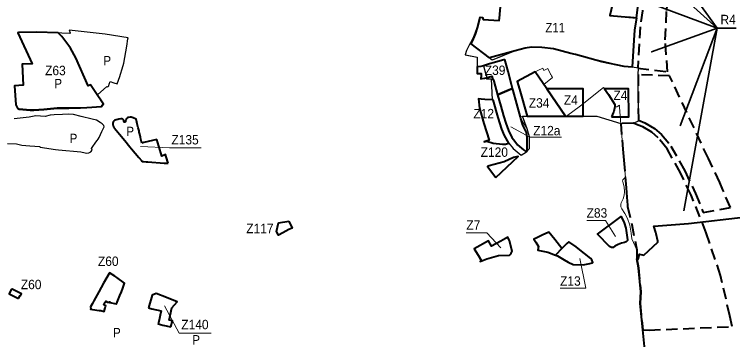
# Model space of a CAD drawing. Extents: x -650276 to -642489, y -1074425 to -1066658.
# Drawn here: x -647044 to -645214, y -1070685 to -1069855 of the extents above; entities that cross this region are included whole.
import ezdxf

# ---------------------------------------------------------------- set-up
doc = ezdxf.new("R2010")
doc.units = 0
doc.header["$LTSCALE"] = 9.6
doc.linetypes.add('MEDIUM_DASHED', pattern=[4.5, 3, -1.5])
for name, color, linetype, lineweight in [('1', 7, 'Continuous', 13), ('4', 7, 'Continuous', 40), ('42', 7, 'Continuous', 25), ('44', 7, 'Continuous', 40), ('45', 7, 'Continuous', 40), ('46', 7, 'Continuous', 13), ('5', 7, 'Continuous', 35), ('60', 7, 'Continuous', 35), ('61', 7, 'MEDIUM_DASHED', 40), ('62', 7, 'Continuous', 35), ('7', 7, 'MEDIUM_DASHED', 40)]:
    doc.layers.add(name, color=color, linetype=linetype, lineweight=lineweight)

msp = doc.modelspace()

# ---------------------------------------------------------------- linework, layer by layer
at = {"layer": '1'}
for points in [[(-645494.12, -1070282.52), (-645494.57, -1070280.34), (-645493.8, -1070277.67), (-645491.94, -1070275.85), (-645487.361, -1070271.37), (-645490.95, -1070226.89), (-645497.23, -1070154.58), (-645499.84, -1070125.33), (-645502.55, -1070091.83), (-645503.04, -1070089.54), (-645502.17, -1070089.16), (-645502.45, -1070087.23), (-645504.06, -1070087.92), (-645509.06, -1070090.97), (-645514.56, -1070090.91), (-645514.49, -1070085.4), (-645530.3, -1070060.08), (-645543.32, -1070041.67), (-645601.8, -1070088.57), (-645637.56, -1070114.89), (-645683.72, -1070114.92), (-645744.39, -1070114.96), (-645749.28, -1070114.96), (-645755.4, -1070117.6), (-645744.75, -1070135.39), (-645737.63, -1070147.39), (-645731.94, -1070167.87), (-645731.3, -1070197.24), (-645739.12, -1070205.9), (-645752.54, -1070214.74), (-645773.48, -1070197.1), (-645784.51, -1070183.77), (-645795.07, -1070164.26), (-645801.99, -1070148.51), (-645811.48, -1070118.65), (-645824.28, -1070073.67), (-645826.615, -1070073.495), (-645828.963, -1070019.709), (-645841.075, -1070020.163), (-645841.89, -1070017.42), (-645841.21, -1070017.31), (-645841.32, -1070013.79), (-645841.43, -1070010.21), (-645842.34, -1070010.22), (-645843.74, -1070010.25), (-645842.8, -1070008.59), (-645849.1, -1069986.42), (-645855.54, -1069988.24), (-645864.77, -1069989.26), (-645864.48, -1069964.53), (-645894.25, -1069958.7), (-645895.66, -1069958.42), (-645892.09, -1069947.98), (-645876.15, -1069916.47), (-645870.89, -1069903.5), (-645865.78, -1069888.76), (-645858.78, -1069862.84), (-645850.92, -1069863.41), (-645849.79, -1069868.4), (-645808.84, -1069870.75), (-645808.28, -1069865.39), (-645806.07, -1069844.09)], [(-645695.39, -1070034), (-645673.1, -1070016.78), (-645675.24, -1070012.51), (-645677.02, -1070008.93), (-645677.65, -1070007.66), (-645684.59, -1069993.87), (-645689.84, -1069996.37), (-645694.8, -1069998.22), (-645697.59, -1069992.31), (-645710.43, -1069998.39), (-645717.36, -1070002.12)], [(-645717.36, -1070002.12), (-645706.41, -1070018.01), (-645695.39, -1070034)], [(-645470.99, -1070428.07), (-645472.61, -1070413.13), (-645476.12, -1070393.13), (-645482.16, -1070375.96), (-645488.99, -1070362.96), (-645496.02, -1070351.15), (-645498, -1070347.74), (-645498.74, -1070345.87), (-645499.09, -1070343.91), (-645499.01, -1070340.96), (-645498.75, -1070338.98), (-645497.83, -1070336.16), (-645495.44, -1070330.67), (-645493.05, -1070326.11), (-645490.03, -1070316.27), (-645489.31, -1070307.77), (-645490.79, -1070294.93), (-645494.12, -1070282.52)], [(-645428.73, -1070758.67), (-645434.53, -1070738.77), (-645449.82, -1070592.72), (-645448.36, -1070563), (-645454.02, -1070501.52), (-645458.46, -1070478.86), (-645458.32, -1070455.91), (-645470.99, -1070428.07)]]:
    msp.add_lwpolyline(points, dxfattribs=at)
at = {"layer": '4'}
for points in [[(-646791.03, -1070128.23), (-646791.64, -1070129), (-646792.11, -1070129.89), (-646792.76, -1070131.79), (-646792.97, -1070133.76), (-646792.84, -1070135.73), (-646792.42, -1070137.71), (-646792.18, -1070138.48), (-646791.84, -1070139.56), (-646791.13, -1070141.44), (-646790.86, -1070142.02), (-646790.29, -1070142.85), (-646784.8, -1070149.86), (-646784.45, -1070150.291)], [(-646748.31, -1070117.83), (-646753.45, -1070118.63), (-646755.74, -1070119.56), (-646757.76, -1070121.07), (-646759.06, -1070122.6), (-646759.78, -1070124), (-646760.32, -1070125.55), (-646760.5, -1070127.58), (-646760.22, -1070129.42), (-646762.07, -1070129.91), (-646763.9, -1070130.41), (-646763.98, -1070130.1), (-646764, -1070129.86), (-646764.94, -1070127.21), (-646765.19, -1070126.23), (-646765.51, -1070125.28), (-646765.97, -1070124.42), (-646767.38, -1070123), (-646768.25, -1070122.53), (-646769.17, -1070122.15), (-646770.43, -1070121.92), (-646772.19, -1070121.98), (-646777.37, -1070122.79), (-646780.28, -1070123.41), (-646784.13, -1070124.41), (-646787, -1070125.38), (-646788.77, -1070126.26), (-646789.61, -1070126.79), (-646791.03, -1070128.23)], [(-646718.8, -1070183.56), (-646721.09, -1070173.94), (-646722.4, -1070168.45), (-646723.4, -1070164.29), (-646724.86, -1070158.17), (-646725.39, -1070155.78), (-646726.17, -1070152.7), (-646728.14, -1070144.51), (-646730.45, -1070134.85), (-646731.54, -1070130.28), (-646733.35, -1070122.79), (-646740.92, -1070119.57), (-646743.33, -1070118.51), (-646745.78, -1070117.96), (-646748.31, -1070117.83)], [(-646784.45, -1070150.291), (-646784.18, -1070150.61), (-646783.937, -1070150.923), (-646775.93, -1070160.78), (-646762.52, -1070177.24)], [(-646762.52, -1070177.24), (-646749.79, -1070193.02), (-646745.61, -1070198.15), (-646726.48, -1070220.46), (-646726.36, -1070220.34), (-646719.7, -1070228.25), (-646717.71, -1070230.56)], [(-646680.68, -1070174.5), (-646713.74, -1070182.36), (-646718.8, -1070183.56)], [(-646651.86, -1070235.22), (-646656.96, -1070218.43), (-646658.64, -1070212.77), (-646667.64, -1070217.36), (-646680.61, -1070174.79), (-646680.68, -1070174.5)], [(-646717.71, -1070230.56), (-646714.42, -1070230.81), (-646708.2, -1070231.25), (-646703.67, -1070231.58), (-646662.41, -1070234.57), (-646651.86, -1070235.22)], [(-646655.95, -1070577.64), (-646682.29, -1070567.36), (-646692.98, -1070571.45), (-646701.87, -1070603.92)], [(-646649.71, -1070634.85), (-646642.32, -1070603.3), (-646628.69, -1070588.27), (-646655.95, -1070577.64)], [(-646701.87, -1070603.92), (-646693.18, -1070605.83), (-646669.59, -1070611.01)], [(-646669.59, -1070611.01), (-646672.13, -1070622.41), (-646673.91, -1070630.38), (-646676.414, -1070641.58)], [(-646676.414, -1070641.58), (-646676.81, -1070643.36), (-646677.13, -1070644.78), (-646665.42, -1070647.54), (-646645.03, -1070652.34)], [(-646645.03, -1070652.34), (-646641.09, -1070636.89), (-646649.71, -1070634.85)]]:
    msp.add_lwpolyline(points, dxfattribs=at)
at = {"layer": '4', "lineweight": 13}
for points in [[(-646567.835, -1070195.719), (-646648.755, -1070195.719), (-646722.263, -1070192.418)], [(-646542.723, -1070668.026), (-646623.643, -1070668.026), (-646660.881, -1070598.727)]]:
    msp.add_lwpolyline(points, dxfattribs=at)
at = {"layer": '42'}
for points in [[(-646753.995, -1069915.425), (-646811.935, -1069906.155), (-646904.446, -1069895.991), (-646901.388, -1069902.723), (-646902.06, -1069902.694), (-646901.388, -1069904.174)], [(-646901.388, -1069904.174), (-646987.56, -1069900.52), (-647032.16, -1069902.13), (-647033.853, -1069902.188)], [(-647033.853, -1069902.188), (-646998.06, -1069980.039), (-646998.716, -1069980.064)], [(-646831.912, -1070060.406), (-646808.49, -1070039.689), (-646805.65, -1070040.439), (-646803.87, -1070038.879), (-646803.43, -1070037.629), (-646801.84, -1070033.139), (-646799.45, -1070026.749), (-646790.27, -1070029.749), (-646781.39, -1070032.779), (-646774.86, -1070014.019), (-646772.96, -1070007.579), (-646768.91, -1069993.979), (-646764.81, -1069980.189), (-646757.45, -1069936.669), (-646754.36, -1069917.669), (-646753.995, -1069915.425)], [(-646998.716, -1069980.064), (-646998.06, -1069981.49), (-647023.975, -1069982.477)], [(-647023.975, -1069982.477), (-647021.27, -1070034.829), (-647021.345, -1070034.832)], [(-647021.345, -1070034.832), (-647021.27, -1070036.28), (-647043.157, -1070037.286)], [(-647043.157, -1070037.286), (-647040.12, -1070084.659), (-647036.03, -1070093.509), (-647034.17, -1070095.039), (-647031.73, -1070095.759), (-647003.49, -1070098.209), (-646993.92, -1070098.039), (-646968.89, -1070096.569), (-646934.63, -1070092.789), (-646904.97, -1070093.069)], [(-646904.97, -1070093.069), (-646874.9, -1070092.649), (-646859.29, -1070091.649), (-646821.89, -1070089.249), (-646817.427, -1070083.656), (-646831.912, -1070061.857), (-646831.305, -1070061.32), (-646831.912, -1070060.406)], [(-647061.2, -1070184.6), (-647038.31, -1070185.73), (-647024.2, -1070188.68), (-647003.89, -1070190.89), (-646978.73, -1070192.54), (-646978.72, -1070193.6), (-646977.7, -1070193.62), (-646977.7, -1070194.45), (-646938.98, -1070199.89), (-646931.25, -1070200.56), (-646874.04, -1070205.5), (-646863.66, -1070208.37), (-646859.54, -1070209.09), (-646853.67, -1070208.44), (-646849.15, -1070205.9), (-646845.3, -1070201.3), (-646847.17, -1070197.38), (-646845.76, -1070194.67), (-646836.06, -1070181.31), (-646832.62, -1070177.08), (-646829.87, -1070173.61), (-646827.95, -1070169.52), (-646820.51, -1070153.68), (-646814.53, -1070141.96), (-646816.06, -1070138.5), (-646820.35, -1070134.43), (-646825.4, -1070130.78), (-646834.04, -1070125.34), (-646845.78, -1070122.84), (-646873.5, -1070115.8), (-646892.87, -1070110.82), (-646904.66, -1070110.24), (-646920.68, -1070110.58), (-646941.99, -1070111.74), (-646952.66, -1070112.57), (-646965.6, -1070115.74), (-646989.24, -1070114.17), (-646989.24, -1070114.17), (-647005.97, -1070117.89), (-647044.19, -1070121.78)]]:
    msp.add_lwpolyline(points, dxfattribs=at)
msp.add_lwpolyline([(-645637.56, -1070114.89), (-645559.63, -1070114.85), (-645499.129, -1070133.293), (-645466.862, -1070133.219), (-645454.051, -1070127.008), (-645455.073, -1070009.111), (-645453.852, -1069992.968), (-645469.701, -1069990.011), (-645490.814, -1069988.074), (-645601.753, -1069962.317), (-645614.072, -1069957.797), (-645625.979, -1069954.92), (-645670.325, -1069943.002), (-645699.889, -1069939.714), (-645726.542, -1069939.398), (-645742.967, -1069941.862), (-645768.424, -1069948.431), (-645826.321, -1069972.247), (-645880.431, -1069930.3), (-645882.381, -1069928.788), (-645892.09, -1069947.98), (-645895.66, -1069958.42), (-645864.48, -1069964.53), (-645864.77, -1069989.26), (-645855.54, -1069988.24), (-645849.1, -1069986.42), (-645842.8, -1070008.59), (-645843.74, -1070010.25), (-645841.43, -1070010.21), (-645841.21, -1070017.31), (-645841.89, -1070017.42), (-645841.075, -1070020.163), (-645828.963, -1070019.709), (-645826.615, -1070073.495), (-645824.28, -1070073.67), (-645811.48, -1070118.65), (-645801.99, -1070148.51), (-645795.07, -1070164.26), (-645784.51, -1070183.77), (-645773.48, -1070197.1), (-645752.54, -1070214.74), (-645739.12, -1070205.9), (-645731.3, -1070197.24), (-645731.94, -1070167.87), (-645737.63, -1070147.39), (-645749.28, -1070114.96), (-645737.075, -1070114.955)], close=True, dxfattribs=at)
at = {"layer": '44'}
msp.add_lwpolyline([(-645497.81, -1070370.93), (-645497.81, -1070370.93), (-645490.19, -1070386.97), (-645486.54, -1070400.38), (-645483.29, -1070417.99), (-645482.62, -1070423.93), (-645481.93, -1070430.04), (-645482.18, -1070432.13), (-645485.67, -1070435.7), (-645489.34, -1070437.05), (-645497.33, -1070438.82), (-645505.88, -1070441.74), (-645513.81, -1070446.24), (-645517.44, -1070449.23), (-645517.95, -1070449.45), (-645520.4, -1070449.87), (-645521.41, -1070449.84), (-645522.95, -1070449.61), (-645524.42, -1070449.16), (-645525.75, -1070448.41), (-645527.34, -1070447.1), (-645558.36, -1070416.1)], close=True, dxfattribs=at)
at = {"layer": '44', "lineweight": 13}
msp.add_lwpolyline([(-645585.63, -1070380.811), (-645537.799, -1070380.811), (-645512.608, -1070421.471)], dxfattribs=at)
msp.add_lwpolyline([(-645585.63, -1070380.811), (-645537.799, -1070380.811), (-645512.608, -1070421.471)], dxfattribs=at)
at = {"layer": '45'}
msp.add_line((-645726.542, -1069939.398), (-645742.967, -1069941.862), dxfattribs=at)
for points in [[(-645500.137, -1069632.833), (-645498, -1069648), (-645495, -1069688), (-645495, -1069744), (-645495, -1069766), (-645504.976, -1069763.332), (-645527, -1069858), (-645459.312, -1069864.01), (-645464.288, -1069895.362), (-645465.756, -1069921.035), (-645469.701, -1069990.011)], [(-645742.967, -1069941.862), (-645768.424, -1069948.431), (-645833, -1069966), (-645880.431, -1069930.3), (-645874.219, -1069917.496), (-645869.262, -1069905.935), (-645863.95, -1069889.468), (-645857.289, -1069863.338), (-645857.204, -1069862.954), (-645850.92, -1069863.41), (-645849.79, -1069868.4), (-645808.84, -1069870.75), (-645808.28, -1069865.39), (-645804.185, -1069825.84)], [(-645469.701, -1069990.011), (-645490.814, -1069988.074), (-645547.4, -1069976.382), (-645614.072, -1069957.797), (-645625.979, -1069954.92), (-645670.325, -1069943.002), (-645699.889, -1069939.714), (-645726.542, -1069939.398)], [(-645833, -1069982), (-645849.1, -1069986.42), (-645855.54, -1069988.24), (-645864.77, -1069989.26), (-645864.97, -1070006.16), (-645854.42, -1070006.47), (-645854.65, -1070010.44), (-645855.17, -1070019.44), (-645852.36, -1070019.01), (-645852.33, -1070019.2), (-645845.37, -1070018.12), (-645845.14, -1070018.08), (-645845.17, -1070017.91), (-645841.89, -1070017.42), (-645827.365, -1070013.291), (-645825.08, -1070021.52)], [(-645833, -1069982), (-645849.1, -1069986.42), (-645855.54, -1069988.24), (-645864.77, -1069989.26), (-645864.97, -1070006.16), (-645854.42, -1070006.47), (-645854.65, -1070010.44), (-645855.17, -1070019.44), (-645852.36, -1070019.01), (-645852.33, -1070019.2), (-645845.37, -1070018.12), (-645845.14, -1070018.08), (-645845.17, -1070017.91), (-645841.89, -1070017.42), (-645827.365, -1070013.291), (-645825.08, -1070021.52)], [(-645794.679, -1069970.596), (-645821, -1069978), (-645833, -1069982)], [(-645794.679, -1069970.596), (-645821, -1069978), (-645833, -1069982)], [(-645777.143, -1070034.287), (-645786.238, -1070001.251), (-645794.679, -1069970.596)], [(-645777.143, -1070034.287), (-645786.238, -1070001.251), (-645794.679, -1069970.596)], [(-645825.08, -1070021.52), (-645823.76, -1070021.67), (-645822.549, -1070025.948), (-645812.76, -1070060.53), (-645783.063, -1070047.855), (-645774.423, -1070044.167), (-645777.143, -1070034.287)], [(-645825.08, -1070021.52), (-645823.76, -1070021.67), (-645822.549, -1070025.948), (-645812.76, -1070060.53), (-645783.063, -1070047.855), (-645774.423, -1070044.167), (-645777.143, -1070034.287)], [(-645772.853, -1070049.868), (-645774.423, -1070044.167), (-645783.063, -1070047.855), (-645812.76, -1070060.53), (-645808.721, -1070074.795), (-645804.52, -1070089.63), (-645797.66, -1070113.88), (-645791.72, -1070132.59)], [(-645737.756, -1070204.389), (-645737.624, -1070169.544), (-645738.79, -1070156.281), (-645748.62, -1070137.889), (-645753.182, -1070121.317), (-645754.333, -1070117.14), (-645772.853, -1070049.868)], [(-645824.28, -1070073.67), (-645845.01, -1070072.12), (-645854.25, -1070071.4), (-645861.74, -1070070.95), (-645858.53, -1070094.64), (-645847.88, -1070133.4)], [(-645795.07, -1070164.26), (-645801.99, -1070148.51), (-645811.48, -1070118.65), (-645824.28, -1070073.67)], [(-645847.88, -1070133.4), (-645834.31, -1070176.15), (-645847.2, -1070180.14), (-645839.82, -1070178.94), (-645824.12, -1070183.63), (-645799.91, -1070186.32), (-645792.37, -1070186.01), (-645784.51, -1070183.77), (-645795.07, -1070164.26)], [(-645791.72, -1070132.59), (-645784.83, -1070151.9), (-645776.26, -1070169.44), (-645771.246, -1070175.64)], [(-645771.246, -1070175.64), (-645761.78, -1070188.29), (-645746.73, -1070201.04), (-645739.12, -1070205.9), (-645737.756, -1070204.389)]]:
    msp.add_lwpolyline(points, dxfattribs=at)
for points in [[(-647032.16, -1069902.13), (-647034.51, -1069902.21), (-646998.06, -1069981.49), (-647024.05, -1069982.48), (-647021.27, -1070036.28), (-647043.25, -1070037.29), (-647040.12, -1070086.11), (-647036.03, -1070094.96), (-647034.17, -1070096.49), (-647031.73, -1070097.21), (-647003.49, -1070099.66), (-646993.92, -1070099.49), (-646968.89, -1070098.02), (-646934.63, -1070094.24), (-646904.97, -1070094.52), (-646874.9, -1070094.1), (-646859.29, -1070093.1), (-646821.89, -1070090.7), (-646817.15, -1070084.76), (-646816.9, -1070084.45), (-646837.65, -1070053.22), (-646849.79, -1070035.17), (-646855.62, -1070037.66), (-646886.85, -1069966.26), (-646900.26, -1069941.64), (-646904.72, -1069935.84), (-646922.79, -1069912.31), (-646931.67, -1069902.89), (-646987.56, -1069900.52)], [(-645639.638, -1070114.895), (-645687.31, -1070045.724), (-645717.36, -1070002.12), (-645762.868, -1070026.606), (-645757.215, -1070045.97), (-645737.075, -1070114.955)], [(-645639.638, -1070114.895), (-645687.31, -1070045.724), (-645717.36, -1070002.12), (-645762.868, -1070026.606), (-645757.215, -1070045.97), (-645737.075, -1070114.955)], [(-645639.638, -1070114.895), (-645594.733, -1070114.868), (-645595.2, -1070045.403), (-645687.31, -1070045.724)], [(-645639.638, -1070114.895), (-645594.733, -1070114.868), (-645595.2, -1070045.403), (-645687.31, -1070045.724)], [(-645522.587, -1070116.952), (-645478.664, -1070117.114), (-645479.429, -1070045.409), (-645540.433, -1070045.752), (-645530.3, -1070060.08), (-645514.49, -1070085.4), (-645514.56, -1070090.91), (-645514.61, -1070094.35), (-645517.02, -1070103.08), (-645518.35, -1070106.87), (-645521.73, -1070114.83)], [(-645522.587, -1070116.952), (-645478.664, -1070117.114), (-645479.429, -1070045.409), (-645540.433, -1070045.752), (-645530.3, -1070060.08), (-645514.49, -1070085.4), (-645514.56, -1070090.91), (-645514.61, -1070094.35), (-645517.02, -1070103.08), (-645518.35, -1070106.87), (-645521.73, -1070114.83)], [(-645816.9, -1070270.96), (-645760.05, -1070217.79), (-645760.91, -1070217.98), (-645772.08, -1070220.39), (-645795.85, -1070231.81), (-645833.92, -1070241.96), (-645838.53, -1070243.19)], [(-646344.93, -1070382.33), (-646336.25, -1070400.875), (-646344.26, -1070403.84), (-646359.769, -1070412.361), (-646370.56, -1070418.29), (-646375.63, -1070408.76), (-646370.624, -1070386.792)], [(-645862.66, -1070469.5), (-645853.98, -1070483.81), (-645856.87, -1070485.24), (-645840.59, -1070479), (-645810.44, -1070470.17), (-645782.57, -1070469.22), (-645780.38, -1070467.64), (-645777.8, -1070464.4), (-645776.04, -1070459.38), (-645782.13, -1070432.59), (-645786.9, -1070423.81), (-645804.58, -1070433.53), (-645828.24, -1070446.54), (-645836.32, -1070432.55), (-645872.35, -1070453.55)], [(-645862.66, -1070469.5), (-645853.98, -1070483.81), (-645856.87, -1070485.24), (-645840.59, -1070479), (-645810.44, -1070470.17), (-645782.57, -1070469.22), (-645780.38, -1070467.64), (-645777.8, -1070464.4), (-645776.04, -1070459.38), (-645782.13, -1070432.59), (-645786.9, -1070423.81), (-645804.58, -1070433.53), (-645828.24, -1070446.54), (-645836.32, -1070432.55), (-645872.35, -1070453.55)], [(-645594.769, -1070494.065), (-645577.47, -1070490.3), (-645571.13, -1070488.89), (-645569.97, -1070488.3), (-645572.86, -1070481.41), (-645575.7, -1070477.77), (-645591.49, -1070465.19), (-645594.62, -1070462.7), (-645612.77, -1070447.82), (-645631.63, -1070435.3), (-645636.42, -1070439.93), (-645648.9, -1070452.38), (-645666.99, -1070429.58), (-645682.02, -1070410.65), (-645699.33, -1070418.25), (-645714.74, -1070425.84), (-645720.48, -1070428.75), (-645715.56, -1070436.27), (-645708.28, -1070447.28), (-645710.14, -1070456.31), (-645684.78, -1070461.52), (-645665.6, -1070469.04), (-645660.29, -1070471.12), (-645643.4, -1070481.02), (-645633.35, -1070486.91), (-645620.22, -1070493)], [(-645594.769, -1070494.065), (-645577.47, -1070490.3), (-645571.13, -1070488.89), (-645569.97, -1070488.3), (-645572.86, -1070481.41), (-645575.7, -1070477.77), (-645591.49, -1070465.19), (-645594.62, -1070462.7), (-645612.77, -1070447.82), (-645631.63, -1070435.3), (-645636.42, -1070439.93), (-645648.9, -1070452.38), (-645665.6, -1070469.04), (-645660.29, -1070471.12), (-645643.4, -1070481.02), (-645633.35, -1070486.91), (-645620.22, -1070493)], [(-646802.19, -1070516.26), (-646816.42, -1070540.49), (-646828.45, -1070562.89), (-646841.16, -1070585.79), (-646844.76, -1070592.54), (-646849.72, -1070600.98), (-646848.99, -1070606.28), (-646849.59, -1070607.4), (-646844.96, -1070607.98), (-646827.88, -1070610.12), (-646822.99, -1070610.51), (-646815.05, -1070613.14), (-646812.5, -1070603.78), (-646811.5, -1070600.29), (-646810.82, -1070598.23), (-646816.11, -1070595.8), (-646814.52, -1070592.78), (-646811.06, -1070586.67), (-646806.41, -1070589), (-646802.06, -1070589.93), (-646801.73, -1070588.37), (-646800.13, -1070588.71), (-646800.47, -1070590.28), (-646784.18, -1070593.76), (-646784, -1070593.34), (-646783.59, -1070593.52), (-646779.9, -1070584.92), (-646774.91, -1070571.88), (-646771.17, -1070562.7), (-646767.63, -1070553.09), (-646762.71, -1070540.85), (-646782.63, -1070526.02), (-646788, -1070522.49), (-646800.94, -1070514.04)], [(-646802.19, -1070516.26), (-646816.42, -1070540.49), (-646828.45, -1070562.89), (-646841.16, -1070585.79), (-646844.76, -1070592.54), (-646849.72, -1070600.98), (-646848.99, -1070606.28), (-646849.59, -1070607.4), (-646844.96, -1070607.98), (-646827.88, -1070610.12), (-646822.99, -1070610.51), (-646815.05, -1070613.14), (-646812.5, -1070603.78), (-646811.5, -1070600.29), (-646810.82, -1070598.23), (-646816.11, -1070595.8), (-646814.52, -1070592.78), (-646811.06, -1070586.67), (-646806.41, -1070589), (-646802.06, -1070589.93), (-646801.73, -1070588.37), (-646800.13, -1070588.71), (-646800.47, -1070590.28), (-646784.18, -1070593.76), (-646784, -1070593.34), (-646783.59, -1070593.52), (-646779.9, -1070584.92), (-646774.91, -1070571.88), (-646771.17, -1070562.7), (-646767.63, -1070553.09), (-646762.71, -1070540.85), (-646782.63, -1070526.02), (-646788, -1070522.49), (-646800.94, -1070514.04)], [(-647032.738, -1070579.83), (-647029.168, -1070572.13), (-647028.248, -1070572.63), (-647025.868, -1070568.26), (-647049.248, -1070555.64), (-647050.098, -1070555.74), (-647050.868, -1070556.59), (-647052.498, -1070559.7), (-647056.518, -1070567.41), (-647056.528, -1070568.32), (-647055.518, -1070569.07)]]:
    msp.add_lwpolyline(points, close=True, dxfattribs=at)
at = {"layer": '46'}
for points in [[(-645649.723, -1070168.46), (-645730.643, -1070168.46), (-645779.318, -1070142.456)], [(-645892.796, -1070412.223), (-645840.481, -1070412.223), (-645804.515, -1070450.215)], [(-645892.796, -1070412.223), (-645840.481, -1070412.223), (-645804.515, -1070450.215)], [(-645653.64, -1070553.576), (-645587.872, -1070553.576), (-645603.567, -1070478.038)], [(-645653.64, -1070553.576), (-645587.872, -1070553.576), (-645603.567, -1070478.038)]]:
    msp.add_lwpolyline(points, dxfattribs=at)
at = {"layer": '5', "lineweight": 40}
for points in [[(-645442.834, -1070659.455), (-645449.82, -1070592.72), (-645448.36, -1070563), (-645454.02, -1070501.52), (-645458.46, -1070478.86), (-645455.09, -1070479.21), (-645451.226, -1070466.394), (-645440.61, -1070469.53), (-645404.4, -1070435.88), (-645404.34, -1070433.93), (-645408.66, -1070414.62), (-645409.38, -1070411.41), (-645414.65, -1070395.37), (-645326.62, -1070388.32), (-645179.26, -1070371.74), (-645006.86, -1070365.38), (-645003.102, -1070365.432), (-645003.03, -1070365.427), (-645001.312, -1070412.099), (-645004.327, -1070461.264), (-645014.277, -1070543.11), (-645023.048, -1070595.033), (-645023.346, -1070596.478)], [(-645435.711, -1070727.497), (-645442.836, -1070659.455), (-645442.834, -1070659.455)]]:
    msp.add_lwpolyline(points, dxfattribs=at)
at = {"layer": '61'}
for points in [[(-645374.642, -1069640.059), (-645376.605, -1069623.944), (-645435.877, -1069633.555), (-645431.642, -1069692.811), (-645434.826, -1069759.235), (-645443.679, -1069846.142), (-645449.445, -1069887.328), (-645455.84, -1069992.731), (-645379.881, -1070001.766), (-645385.95, -1069920.347), (-645382.14, -1069845.883), (-645378.587, -1069802.788), (-645374.542, -1069758.923), (-645371.563, -1069692.39)], [(-645504.976, -1069763.332), (-645527, -1069858), (-645464.93, -1069863.477), (-645459.312, -1069864.01), (-645456.586, -1069844.534), (-645451.227, -1069795.473), (-645448.864, -1069769.837), (-645466.353, -1069769.337), (-645478.997, -1069768.976), (-645482.753, -1069768.26), (-645495, -1069766)], [(-645374.685, -1070012.289), (-645455.073, -1070009.111), (-645454.066, -1070125.249), (-645437.885, -1070131.669), (-645413.129, -1070146.351), (-645394.98, -1070161.51), (-645371.209, -1070191.309), (-645336.176, -1070254.367), (-645308.702, -1070311.792), (-645289.153, -1070360.302), (-645219.594, -1070347.682), (-645238.856, -1070303.185), (-645246.433, -1070284.382), (-645275.729, -1070223.153)]]:
    msp.add_lwpolyline(points, close=True, dxfattribs=at)
at = {"layer": '62'}
for q in [(-645338.143, -1070356.741), (-645205.454, -1069890.903)]:
    msp.add_line((-645253.165, -1069890.903), q, dxfattribs=at)
msp.add_lwpolyline([(-645205.454, -1069890.903), (-645253.165, -1069890.903), (-645480.406, -1069576.285), (-645253.165, -1069890.903), (-645466.774, -1069697.69), (-645253.165, -1069890.903), (-645479.043, -1069805.455), (-645253.165, -1069890.903), (-645420.426, -1069951.415), (-645253.165, -1069890.903), (-645348.178, -1070139.662)], dxfattribs=at)
at = {"layer": '7'}
msp.add_lwpolyline([(-645499.142, -1070133.293), (-645493.76, -1070199.15), (-645490.95, -1070226.89), (-645485.21, -1070298.03), (-645483.34, -1070321.17), (-645481.65, -1070342.07), (-645481.67, -1070345.39), (-645471, -1070391), (-645458.32, -1070455.91), (-645458.46, -1070478.86), (-645454.02, -1070501.52), (-645448.36, -1070563), (-645449.82, -1070592.72), (-645444.47, -1070643.85), (-645442.836, -1070659.455), (-645426.34, -1070660.33), (-645214.903, -1070651.431), (-645221.272, -1070623.729), (-645244.808, -1070521.357), (-645281.252, -1070412.013), (-645319.69, -1070316.63), (-645346.844, -1070259.875), (-645381.213, -1070198.011), (-645403.604, -1070169.942), (-645420.081, -1070156.179), (-645443.191, -1070142.473), (-645454.881, -1070137.836), (-645466.862, -1070133.22)], close=True, dxfattribs=at)

# ---------------------------------------------------------------- texts
at = {"layer": '4', "width": 0.95}
for s, p in [('Z135', (-646643.568, -1070187.052)), ('Z140', (-646618.457, -1070658.164))]:
    msp.add_text(s, height=24, dxfattribs=at).set_placement(p)
at = {"layer": '44', "width": 0.95}
msp.add_text('Z83', height=24, dxfattribs=at).set_placement((-645586.057, -1070373.732))
msp.add_text('Z83', height=24, dxfattribs=at).set_placement((-645586.057, -1070373.732))
at = {"layer": '45', "width": 0.9}
msp.add_text('Z11', height=24, dxfattribs=at).set_placement((-645690.933, -1069901.172))
at = {"layer": '46', "width": 0.95}
for s, p in [('Z63', (-646965.327, -1070010.57)), ('Z39', (-645845.387, -1070009.975)), ('Z39', (-645845.387, -1070009.975)), ('Z4', (-645517.623, -1070073.78)), ('Z4', (-645517.623, -1070073.78)), ('Z34', (-645733.26, -1070093.266)), ('Z34', (-645733.26, -1070093.266)), ('Z4', (-645644.02, -1070085.964)), ('Z4', (-645644.02, -1070085.964)), ('Z12', (-645874.409, -1070120.563)), ('Z12a', (-645722.15, -1070163.87)), ('Z120', (-645855.898, -1070218.668)), ('Z117', (-646453.122, -1070413.348)), ('Z7', (-645892.427, -1070404.622)), ('Z7', (-645892.427, -1070404.622)), ('Z60', (-646830.725, -1070496.795)), ('Z60', (-647027.184, -1070556.06)), ('Z13', (-645653.625, -1070547.221))]:
    msp.add_text(s, height=24, dxfattribs=at).set_placement(p)
at = {"layer": '60', "width": 0.9}
for p in [(-646816.629, -1069985.717), (-646816.629, -1069985.717), (-646941.403, -1070043.945), (-646941.403, -1070043.945), (-646758.187, -1070165.956), (-646902.585, -1070183.692), (-646902.585, -1070183.692), (-646791.982, -1070678.937), (-646791.982, -1070678.937), (-646590.032, -1070697.137)]:
    msp.add_text('P', height=24, dxfattribs=at).set_placement(p)
at = {"layer": '62', "width": 0.95}
msp.add_text('R4', height=24, dxfattribs=at).set_placement((-645245.139, -1069880.683))

doc.saveas('drawing.dxf')
